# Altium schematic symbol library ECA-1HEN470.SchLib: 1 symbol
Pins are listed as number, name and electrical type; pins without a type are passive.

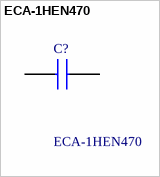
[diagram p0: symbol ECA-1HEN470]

## ECA-1HEN470
designator C?
Aluminium Electrolytic Capacitors - Radial Leaded Al Lytic Cap, Radial GA(Bi-polar) Series; Manufacturer_Name: Panasonic; Geometry.Height: 13.5mm
footprint CAPPRD500W65D1000H1350
pins: 1 +, 2 -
